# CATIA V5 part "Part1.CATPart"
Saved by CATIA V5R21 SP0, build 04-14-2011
Part number: Part1
Bounding box of the stored display mesh (mm): x 0 to 0, y -90 to 90, z -80.981 to 80.981
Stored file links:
  C:\Users\RIAD MAHAMUD PIASH\Desktop\Part1.CATPart
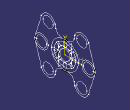
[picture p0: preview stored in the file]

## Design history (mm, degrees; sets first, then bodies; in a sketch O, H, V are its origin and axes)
Body1 (main body)
  Sketch1 on yz-plane, origin (0, 0, 0), H (0, 1, 0), V (0, 0, 1)
    circle A1 centre (70, 0) radius 20
    point P1 (70, 0)
    point P2 (89.0713, -6.0238)
    line L1 (89.0713, -6.0238) -> (70.0249, -66.325)
    point P3 (70.0249, -66.325)
    arc A2 centre (50, -60) radius 21 from (70.0249, -66.325) to (29.5073, -64.5878) cw
    point P4 (50, -60)
    point P5 (29.5073, -64.5878)
    line L2 (29.5073, -64.5878) -> (27.386, -55.1124)
    point P6 (27.386, -55.1124)
    arc A3 centre (7.8691, -59.4817) radius 20 from (27.386, -55.1124) to (5.2461, -39.6545) ccw
    point P8 (3.6763, -39.9262)
    line L3 (1.6061, -39.9677) -> (0, -40)
    point P9 (0, -40)
    point P10 (-3.6763, -39.9262)
    point P11 (-27.386, -55.1124)
    arc A4 centre (-7.8691, -59.4817) radius 20 from (-27.386, -55.1124) to (-5.2461, -39.6545) cw
    point P13 (-29.5073, -64.5878)
    point P14 (-70.0249, -66.325)
    arc A5 centre (-50, -60) radius 21 from (-70.0249, -66.325) to (-29.5073, -64.5878) ccw
    line L4 (-29.5073, -64.5878) -> (-27.386, -55.1124)
    point P16 (-89.0713, -6.0238)
    line L5 (-89.0713, -6.0238) -> (-70.0249, -66.325)
    point P17 (89.0713, 6.0238)
    point P18 (70.0249, 66.325)
    point P20 (29.5073, 64.5878)
    point P21 (27.386, 55.1124)
    point P23 (0, 40)
    point P24 (-27.386, 55.1124)
    point P26 (-29.5073, 64.5878)
    point P27 (-70.0249, 66.325)
    point P29 (-89.0713, 6.0238)
    line L6 (89.0713, 6.0238) -> (70.0249, 66.325)
    arc A6 centre (50, 60) radius 21 from (70.0249, 66.325) to (29.5073, 64.5878) ccw
    line L7 (29.5073, 64.5878) -> (27.386, 55.1124)
    arc A7 centre (7.8691, 59.4817) radius 20 from (27.386, 55.1124) to (5.2461, 39.6545) cw
    line L8 (1.6061, 39.9677) -> (0, 40)
    arc A8 centre (-7.8691, 59.4817) radius 20 from (-27.386, 55.1124) to (-5.2461, 39.6545) ccw
    arc A9 centre (-50, 60) radius 21 from (-70.0249, 66.325) to (-29.5073, 64.5878) cw
    line L9 (-29.5073, 64.5878) -> (-27.386, 55.1124)
    line L10 (-89.0713, 6.0238) -> (-70.0249, 66.325)
    circle A10 centre (50, -60) radius 15
    circle A11 centre (-50, -60) radius 15
    circle A12 centre (-50, 60) radius 15
    circle A13 centre (50, 60) radius 15
    circle A14 centre (-70, 0) radius 20
    circle A15 centre (0, 0) radius 40
    arc A16 centre (0, 0) radius 21 from (12.5756, 16.8183) to (3, 20.7846) ccw
    arc A17 centre (0, 0) radius 32 from (20.4064, 24.6491) to (3, 31.8591) ccw
    circle A18 centre (0, 0) radius 16
    point P34 (35.0533, 39.296)
    arc A19 centre (0, 0) radius 21 from (-12.5756, -16.8183) to (-3, -20.7846) ccw
    arc A20 centre (0, 0) radius 32 from (-20.4064, -24.6491) to (-3, -31.8591) ccw
    arc A21 centre (0, 0) radius 32 from (-24.6491, 20.4064) to (-31.8591, 3) ccw
    arc A22 centre (0, 0) radius 21 from (16.8183, -12.5756) to (20.7846, -3) ccw
    arc A23 centre (0, 0) radius 21 from (-16.8183, 12.5756) to (-20.7846, 3) ccw
    arc A24 centre (0, 0) radius 32 from (24.6491, -20.4064) to (31.8591, -3) ccw
    arc A25 centre (0, 0) radius 32 from (-3, 31.8591) to (-20.4064, 24.6491) ccw
    arc A26 centre (0, 0) radius 21 from (-3, 20.7846) to (-12.5756, 16.8183) ccw
    arc A27 centre (0, 0) radius 21 from (3, -20.7846) to (12.5756, -16.8183) ccw
    arc A28 centre (0, 0) radius 32 from (3, -31.8591) to (20.4064, -24.6491) ccw
    line L11 (3, -20.7846) -> (3, -31.8591)
    line L12 (-3, -20.7846) -> (-3, -31.8591)
    line L13 (-12.5756, -16.8183) -> (-20.4064, -24.6491)
    line L14 (-24.6491, -20.4064) -> (-16.8183, -12.5756)
    line L15 (-24.6491, 20.4064) -> (-16.8183, 12.5756)
    line L16 (-20.4064, 24.6491) -> (-12.5756, 16.8183)
    line L17 (-3, 31.8591) -> (-3, 20.7846)
    line L18 (3, 31.8591) -> (3, 20.7846)
    line L19 (20.4064, 24.6491) -> (12.5756, 16.8183)
    point P60 (12.5756, 16.8183)
    line L20 (16.8183, 12.5756) -> (24.6491, 20.4064)
    line L21 (16.8183, -12.5756) -> (24.6491, -20.4064)
    line L22 (12.5756, -16.8183) -> (20.4064, -24.6491)
    line L23 (-31.8591, -3) -> (-20.4064, -3)
    point P62 (-31.8591, -3)
    line L24 (-20.7846, 3) -> (-31.8591, 3)
    point P64 (-20.7846, 3)
    point P65 (-31.8591, 3)
    line L25 (20.7846, 3) -> (31.8591, 3)
    point P66 (20.7846, 3)
    point P67 (31.8591, 3)
    line L26 (20.7846, -3) -> (31.8591, -3)
    point P68 (20.7846, -3)
    point P69 (31.8591, -3)
    arc A29 centre (0, 0) radius 21 from (20.7846, 3) to (16.8183, 12.5756) ccw
    arc A30 centre (0, 0) radius 32 from (31.8591, 3) to (24.6491, 20.4064) ccw
    arc A31 centre (0, 0) radius 21 from (-20.7846, -3) to (-16.8183, -12.5756) ccw
    arc A32 centre (0, 0) radius 32 from (-31.8591, -3) to (-24.6491, -20.4064) ccw
    point P77 (-5.2461, -39.6545)
    point P78 (5.2461, -39.6545)
    point P79 (1.6061, -39.9677)
    point P80 (-5.2461, 39.6545)
    point P81 (1.6061, 39.9677)
    point P82 (5.2461, 39.6545)
    circle A33 centre (70, 0) radius 15
    circle A34 centre (-70, 0) radius 15
    radius A1 = 20
    radius A2 = 21
    radius A3 = 20
    distance P4 H = 60
    distance P1 V = 70
    distance P4 V = 50
    distance P9 H = 40
    radius A10 = 15
    radius A15 = 40
    radius A17 = 32
    radius A16 = 21
    radius A18 = 16
    radius A33 = 15
    coincidence: P1 H, P2 A1, P9 V, P34 L8, A16 A19, A17 A20, A17 A21, A19 A22, A16 A23, A20 A24, A17 A25, A16 A26, A19 A27, A20 A28, P60 A16, P62 A21, P64 A23, P65 A21, P66 A22, P67 A24, P68 A22, P69 A24, A22 A29, A24 A30, A23 A31, A21 A32, A15 P77, A15 P78, A15 P79, A15 P80, A15 P81, A15 P82
    tangency: L1 A1, A2 L1, L2 A2, A3 L2, L3 A2, A4 A15
    symmetry: P8 P10 V, P6 P11 V, A3 A4 V, P5 P13 V, P3 P14 V, A2 A5 V, L2 L4 V, P2 P16 V, L1 L5 V, P2 P17 H, P3 P18 H, P5 P20 H, P6 P21 H, P9 P23 H, P11 P24 H, P13 P26 H, P14 P27 H, P16 P29 H, L1 L6 H, A2 A6 H, L2 L7 H, A3 A7 H, L3 L8 H, A4 A8 H, A5 A9 H, L4 L9 H, L5 L10 H, A10 A11 V, A11 A12 H, A10 A13 H, A1 A14 V, A33 A34 V
    vertical: L11 V, L12 V, L17 V, L18 V
    horizontal: L23 H, L24 H, L25 H, L26 H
